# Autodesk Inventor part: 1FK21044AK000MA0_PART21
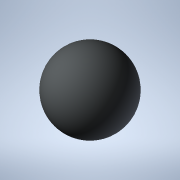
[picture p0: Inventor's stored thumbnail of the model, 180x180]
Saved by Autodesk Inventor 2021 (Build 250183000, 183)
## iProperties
Created: 2025-04
Part Number: 1FK21044AK000MA0_PART21
Material: Generic
Catalog Web Link: www.3dfindit.com
Description: -Servo synchronous motor
Document SubType Name: Modeling
Designer: psAdmin
Mass: 0.137258 g
Surface Area: 1.2868 cm^2
Volume: 0.137258 cm^3
Density: 1 g/cm^3
Appearance: PSOLRGB-212-217-219
Category: PARTsolutions
Title: 1FK21044AK000MA0_PART21
Author: Cadenas PARTsolutions
Comments: Servo synchronous motor
Sending System: PARTsolutions
Preprocessor: ST-DEVELOPER v19.3
PSOL_IDENT_0: {$CADENAS_DATA/23d-libs/siemens_ag/_cat_/87/f4/1fk21044ak000ma0.prj},216 {VTYP=3D},{NB=1FK21044AK000
PSOL_IDENT_1: MA0_PART21},{LINA=1FK21044AK000MA0_PART21},{NN=1FK21044AK000MA0_PART21},{NOPRJ=TRUE},{DATE=19.08.202
PSOL_IDENT_2: 5 14:00:48},{GEOMDATE=30.07.2025 02:00:50},{VERSION=},{LINEID=10},{WBVAR=},{WBNUMERIC=}  {NB=1FK2104
PSOL_IDENT_3: 4AK000MA0_PART21},{LINA=1FK21044AK000MA0_PART21},{KT=DUMMY},{PREVIEW=../../../_pool_/cb/72/p_d211_xx
PSOL_IDENT_4: _00434j.png},{DESCSHORT=SIMOTICS S-1FK2 HD, SINAMICS S210 3AC 400V-480V, 0.95 Nm, 6000 rpm},{DESCLON
PSOL_IDENT_5: G=SIMOTICS S-1FK2 HD servo motor M0=1.27 Nm; PN = 0.6 kW at nN=6000 rpm (380-480 V); PN = 0.4 kW at
PSOL_IDENT_6: nN=3000 rpm (200-240 V); degree of protection IP64; cylindrical shaft D19x40mm; absolute encoder 22-
PSOL_IDENT_7: bit + 12-bit multiturn (encoder AM22DQC); with OCC interface; plug size M17, rotatable; SIMOTICS S-1
PSOL_IDENT_8: FK2 servomotorfor a wide range of uses in industrial environments. SIMOTICS S‑1FK2 servomotors are c
PSOL_IDENT_9: ompact synchronous motors with a high dynamic performance that set themselves apart as a result of t
PSOL_IDENT_10: heir high power density, degree of protection and overload capability. The motors are available in t
PSOL_IDENT_11: wo variants: as High Dynamic variant (highest dynamic performance as a result of the low intrinsic m
PSOL_IDENT_12: oment of inertia for applications demanding a high dynamic performance with low moved masses) - and
PSOL_IDENT_13: as Compact variant (precise and stable closed-loop control for medium up to large moved masses as a
PSOL_IDENT_14: result of a medium intrinsic moment of inertia). SIMOTICSS‑1FK2 servomotors fully exploit their stre
PSOL_IDENT_15: ngths in a system with the SINAMICSS210 frequency converter and simple connection using the one cabl
PSOL_IDENT_16: e connection (OCC). Advantages include the short control and positioning times, fast and precise cor
PSOL_IDENT_17: rection of disturbing quantities as well as stable control with a high dynamic performance. The serv
PSOL_IDENT_18: o motors can be configured to address a wide range of requirements. For example with and without hol
PSOL_IDENT_19: ding brake, IP64 or IP65 degree of protection, singleturn or multiturn absolute encoders - to name j
PSOL_IDENT_20: ust a few. Further, the servomotors are available in different shaft heights extending from 20 to 10
PSOL_IDENT_21: 0. A shaft sealing ring is available to achieve an IP65 degree of protection and for subsequent moun
PSOL_IDENT_22: ting at the motor or as spare part. SIMOTICS - the optimum motor for each and every motion control a
PSOL_IDENT_23: pplication.},{INTNO=195125056312},{SUPPLIERALTNO=1FK2104-4AK00-0MA0},{MANUID=1FK21044AK000MA0},{MANU
PSOL_IDENT_24: NAME=Siemens},{MANUTYPEDESC=Synchronous motor 1FK2-HD 1,27 Nm},{AAU732=SIMOTICS},{AAO057=S-1FK2},{AA
PSOL_IDENT_25: U734=SIMOTICS S-1FK2 HD servo motor M0=1.27 Nm; PN = 0.6 kW at nN=6000 rpm (380-480 V); PN = 0.4 kW
PSOL_IDENT_26: at nN=3000 rpm (200-240 V); degree of protection IP64; cylindrical shaft D19x40mm; absolute encoder
PSOL_IDENT_27: 22-bit + 12-bit multiturn (encoder AM22DQC); with OCC interface; plug size M17, rotatable;},{AAW338=
PSOL_IDENT_28: Synchronous motor 1FK2-HD 1,27 Nm},{AAO742=SIMOTICS},{AAO663=4042948690994},{NOCUPEROU=1},{PRICEQUAN
PSOL_IDENT_29: TITY=1},{QUANTITYMIN=1},{QUANTITYINT=1},{CTN=85015100},{COO=DE},{AAO676=1FK2104-4AK00-0MA0},{AAO677=
PSOL_IDENT_30: Siemens AG},{ORDERUNIT=C62},{CONTENTUNIT=C62}
NB: 1FK21044AK000MA0_PART21
NT: Servo synchronous motor
NBSYN: $MANUID._PART21
LINA: 1FK21044AK000MA0_PART21
CATALOG: SIEMENS
PREVIEW: ../../../_pool_/cb/72/p_d211_xx_00434j.png
DESCSHORT: SIMOTICS S-1FK2 HD, SINAMICS S210 3AC 400V-480V, 0.95 Nm, 6000 rpm
DESCLONG: SIMOTICS S-1FK2 HD servo motor M0=1.27 Nm; PN = 0.6 kW at nN=6000 rpm (380-480 V); PN = 0.4 kW at nN=3000 rpm (200-240 V); degree of protection IP64; cylindrica
INTNO: 195125056312
SUPPLIERALTNO: 1FK2104-4AK00-0MA0
MANUID: 1FK21044AK000MA0
MANUNAME: Siemens
MANUTYPEDESC: Synchronous motor 1FK2-HD 1,27 Nm
AAU732: SIMOTICS
AAO057: S-1FK2
AAU734: SIMOTICS S-1FK2 HD servo motor M0=1.27 Nm; PN = 0.6 kW at nN=6000 rpm (380-480 V); PN = 0.4 kW at nN=3000 rpm (200-240 V); degree of protection IP64; cylindrica
AAW338: Synchronous motor 1FK2-HD 1,27 Nm
AAO742: SIMOTICS
AAO663: 4042948690994.0
NOCUPEROU: 1
PRICEQUANTITY: 1
QUANTITYMIN: 1
QUANTITYINT: 1
CTN: 85015100
COO: DE
ARTICLENO: 1FK21044AK000MA0_PART21
BOMINFO: 1FK21044AK000MA0_PART21
CREATOR: CADENAS GmbH
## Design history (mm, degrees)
feature "2025_04_17_15_37_40_0588"
body "Solid1"
